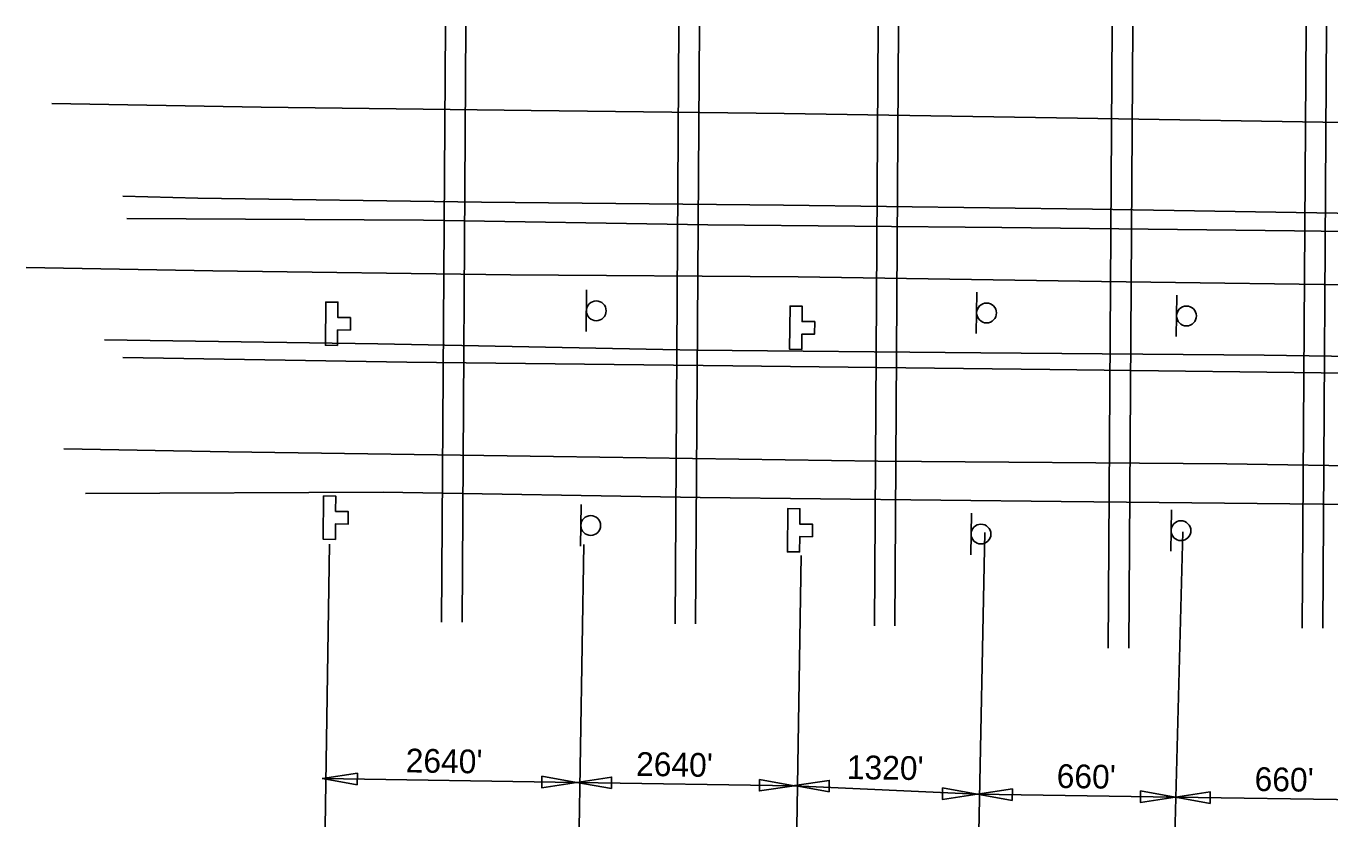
# Model space of a CAD drawing. Extents: x 2155255 to 2162649, y 140388 to 141878.
# Drawn here: x 2158306.4 to 2158635.8, y 141383.9 to 141584.4 of the extents above; entities that cross this region are included whole.
import ezdxf

# ---------------------------------------------------------------- set-up
doc = ezdxf.new("R2010")
doc.units = 0
for name, color, linetype in [('Default', 7, 'Continuous'), ('PR_Dimensions', 7, 'Continuous'), ('PR_Dimensions_Phase4', 7, 'Continuous'), ('PR_Traffic_Control_Devices_Temp_Ph4', 7, 'Continuous'), ('T_PHASE_4', 7, 'Continuous'), ('TOPO_Asphalt', 7, 'Continuous')]:
    doc.layers.add(name, color=color, linetype=linetype)

# ---------------------------------------------------------------- blocks, each defined once
blk = doc.blocks.new('Arrowhd')
at = {"layer": 'Default'}
blk.add_lwpolyline([(0.318, -0.053), (0.318, 0.053), (0, 0)], close=True, dxfattribs=at)
blk = doc.blocks.new('PR-TCSIGN')
at = {"layer": 'Default'}
blk.add_line((17.8, 8.5), (-17.8, 8.5), dxfattribs=at)
blk.add_circle((0, 0), 8.47, dxfattribs=at)
blk = doc.blocks.new('PR-TCSIGN_rev')
at = {"layer": 'Default'}
blk.add_lwpolyline([(-5.47, 0), (-1.58, 0), (-1.58, -3.22), (1.58, -3.22), (1.58, 0), (5.47, 0), (5.47, 3.06), (-5.47, 3.06)], close=True, dxfattribs=at)
blk.add_lwpolyline([(1.58, 0), (5.47, 0), (5.47, 3.06), (-5.47, 3.06), (-5.47, 0), (-1.58, 0), (-1.58, -3.22), (1.58, -3.22), (1.58, 0)], dxfattribs=at)

msp = doc.modelspace()

# ---------------------------------------------------------------- linework, layer by layer
at = {"layer": 'PR_Dimensions'}
for p, q in [((2158411.36, 141433.69), (2158412.32, 141584.38)), ((2158416.53, 141433.66), (2158417.49, 141584.38)), ((2158470.38, 141433.29), (2158471.34, 141584.38)), ((2158475.55, 141433.25), (2158476.52, 141584.38)), ((2158520.7, 141432.77), (2158521.66, 141584.38)), ((2158525.87, 141432.74), (2158526.84, 141584.38)), ((2158579.8, 141427.13), (2158580.8, 141584.38)), ((2158584.97, 141427.1), (2158585.97, 141584.38)), ((2158628.83, 141432.18), (2158629.8, 141584.38)), ((2158634, 141432.14), (2158634.97, 141584.38))]:
    msp.add_line(p, q, dxfattribs=at)
at = {"layer": 'PR_Dimensions_Phase4'}
for p, q in [((2158548.61, 141456.37), (2158545.43, 141299.09)), ((2158598.61, 141456.5), (2158596.17, 141362.3)), ((2158383.03, 141453.4), (2158380.14, 141267.68)), ((2158447.3, 141453.3), (2158444.18, 141259.72)), ((2158502.25, 141450.51), (2158500.07, 141313.4)), ((2158445.45, 141393.18), (2158381.21, 141394.16)), ((2158500.44, 141392.35), (2158445.45, 141393.18)), ((2158546.7, 141390.2), (2158500.44, 141392.35)), ((2158596.7, 141389.45), (2158546.7, 141390.2)), ((2158646.69, 141388.69), (2158596.7, 141389.45))]:
    msp.add_line(p, q, dxfattribs=at)
at = {"layer": 'TOPO_Asphalt'}
for points in [[(2158312.89, 141564.78), (2158365.75, 141563.86), (2158434.03, 141563.05), (2158497.94, 141562.28), (2158572.06, 141561.12), (2158644.35, 141559.9), (2158720.43, 141558.92), (2158985.77, 141558.17)], [(2158985.77, 141535.17), (2158725.88, 141535.87), (2158647.89, 141536.9), (2158575.8, 141538.08), (2158497.77, 141539.11), (2158421.43, 141539.85), (2158349.81, 141540.9), (2158330.84, 141541.37)], [(2158331.86, 141535.76), (2158406.77, 141535.3), (2158478.6, 141534.17), (2158552.92, 141533.47), (2158626.87, 141532.59), (2158694.45, 141531.81), (2158985.77, 141530.96)], [(2158985.77, 141516.93), (2158721.31, 141518.29), (2158652.98, 141518.78), (2158578.1, 141519.84), (2158501.48, 141521.01), (2158428.81, 141521.5), (2158353.61, 141522.5), (2158306.39, 141523.33)], [(2158985.77, 141499), (2158985.31, 141499), (2158698.69, 141500), (2158619.19, 141501.16), (2158547.58, 141501.76), (2158475.74, 141502.47), (2158395.23, 141504.06), (2158326.18, 141505.05)], [(2158330.84, 141500.56), (2158402.62, 141499.42), (2158484.94, 141498.5), (2158565.02, 141497.54), (2158647.34, 141496.57), (2158730.79, 141495.58), (2158985.77, 141494.57)], [(2158985.77, 141471.36), (2158692.13, 141472.41), (2158609.72, 141473.71), (2158521.58, 141474.42), (2158439.64, 141475.58), (2158357.5, 141476.78), (2158315.95, 141477.54)], [(2158321.4, 141466.21), (2158396.62, 141466.56), (2158476.66, 141465.22), (2158567.91, 141464.22), (2158650.39, 141463.34), (2158736.53, 141462.03), (2158985.77, 141461.2)]]:
    msp.add_lwpolyline(points, dxfattribs=at)

# ---------------------------------------------------------------- block references
at = {"layer": 'PR_Dimensions_Phase4'}
for p, xscale, yscale, rotation in [((2158381.3, 141394.17), 27.559000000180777, 27.55900000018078, -0.8665098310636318), ((2158445.45, 141393.18), 27.559000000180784, 27.559000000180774, 179.13349016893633), ((2158445.45, 141393.18), 27.559000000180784, 27.559000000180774, 179.13349016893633), ((2158445.54, 141393.2), 27.559000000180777, 27.55900000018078, -0.8665098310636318), ((2158500.44, 141392.35), 27.559000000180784, 27.559000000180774, 179.13349016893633), ((2158500.54, 141392.37), 27.559000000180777, 27.55900000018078, -0.8665098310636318), ((2158546.7, 141390.2), 27.559000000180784, 27.559000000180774, 179.13349016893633), ((2158546.8, 141390.22), 27.559000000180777, 27.55900000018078, -0.8665098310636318), ((2158596.7, 141389.45), 27.559000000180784, 27.559000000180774, 179.13349016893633), ((2158596.79, 141389.46), 27.559000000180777, 27.55900000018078, -0.8665098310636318)]:
    msp.add_blockref('Arrowhd', p, dxfattribs=dict(at, xscale=xscale, yscale=yscale, rotation=rotation))
at = {"layer": 'PR_Traffic_Control_Devices_Temp_Ph4', "xscale": 0.29527500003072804, "yscale": 0.2952750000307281, "rotation": 89.1334901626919}
for p in [(2158450.44, 141512.4), (2158549.05, 141511.85), (2158599.56, 141511.09), (2158449.05, 141458.13), (2158547.64, 141455.97), (2158598.17, 141456.82)]:
    msp.add_blockref('PR-TCSIGN', p, dxfattribs=at)
at = {"layer": 'PR_Traffic_Control_Devices_Temp_Ph4', "rotation": 89.4985074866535}
for p in [(2158385.11, 141509.13), (2158502.41, 141508.11), (2158384.57, 141460.09), (2158501.85, 141456.91)]:
    msp.add_blockref('PR-TCSIGN_rev', p, dxfattribs=at)

# ---------------------------------------------------------------- texts
at = {"layer": 'T_PHASE_4'}
for s, p in [("2640'", (2158402.27, 141395.73)), ("2640'", (2158460.47, 141394.85)), ("1320'", (2158513.72, 141394.05)), ("660'", (2158566.74, 141391.8)), ("660'", (2158616.74, 141391.04))]:
    msp.add_text(s, height=6, rotation=359.1335, dxfattribs=at).set_placement(p)

doc.saveas('drawing.dxf')
